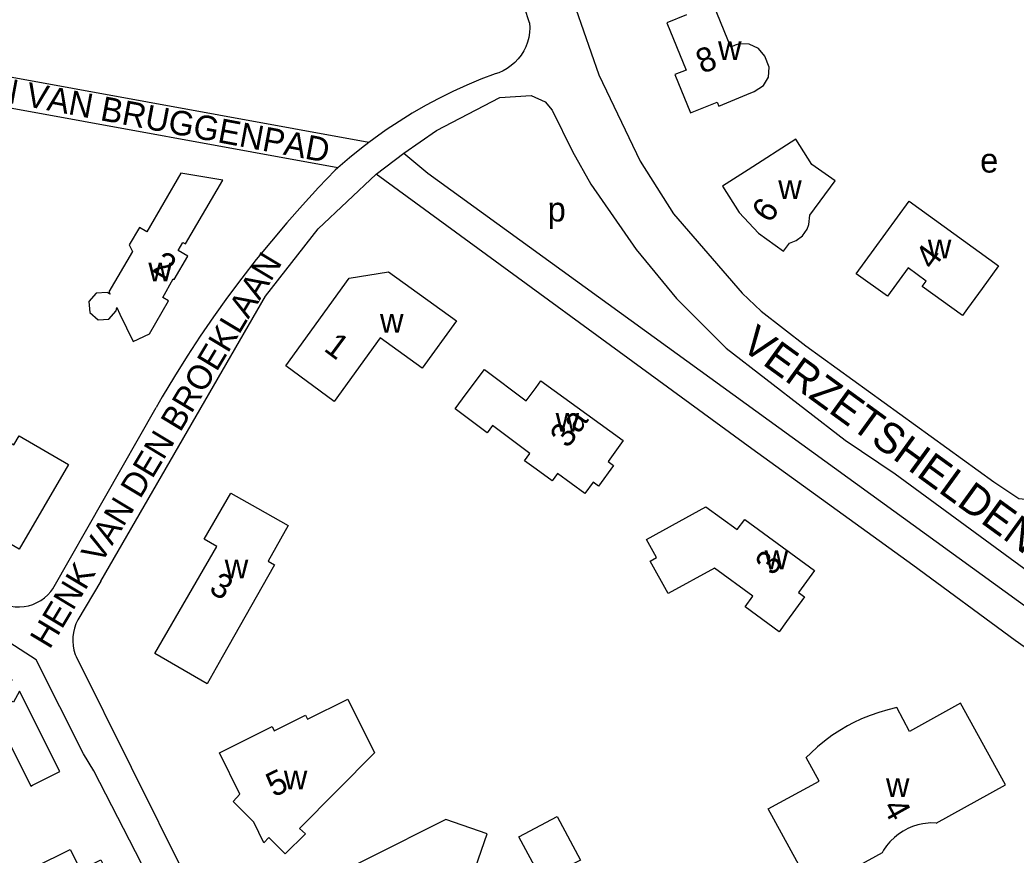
# Model space of a CAD drawing. Extents: x 156721 to 158827, y 386657 to 388950.
# Drawn here: x 158415.3 to 158578.8, y 387103.3 to 387240.4 of the extents above; entities that cross this region are included whole.
import ezdxf

# ---------------------------------------------------------------- set-up
doc = ezdxf.new("R2010")
doc.units = 0
for name, color, linetype in [('BLT_Basislijn', 7, 'Continuous'), ('BLT_Bebouwing', 7, 'Continuous'), ('BLT_Centroide', 7, 'Continuous'), ('BLT_Huisnummer', 7, 'Continuous'), ('BLT_Straatnaam', 7, 'Continuous'), ('BLT_Straatnaam_verkleind', 7, 'Continuous')]:
    doc.layers.add(name, color=color, linetype=linetype)

msp = doc.modelspace()

# ---------------------------------------------------------------- linework, layer by layer
at = {"layer": 'BLT_Basislijn'}
for p, q in [((158472.56, 387220.28), (158410.32, 387231.61)), ((158467.47, 387216.13), (158409.43, 387226.69)), ((158473.74, 387215.05), (158478.32, 387218.52)), ((158467.47, 387216.13), (158467, 387215.7)), ((158420.66, 387147), (158437.63, 387176.77)), ((158428.56, 387148.23), (158424.77, 387141.89)), ((158424.49, 387135.91), (158447.26, 387090.06))]:
    msp.add_line(p, q, dxfattribs=at)
for points in [[(158505.3, 387245.88), (158510.3, 387231.39), (158517.1, 387217.21), (158519.85, 387212.88)], [(158498.93, 387239.89), (158498.12, 387242.44), (158498.08, 387242.56)], [(158498.93, 387239.89), (158498.97, 387239.1), (158498.93, 387238.3), (158498.81, 387237.52), (158498.61, 387236.75), (158498.34, 387236), (158497.99, 387235.29), (158497.57, 387234.61), (158497.09, 387233.99), (158496.54, 387233.41), (158495.94, 387232.89), (158495.29, 387232.43), (158494.6, 387232.04), (158493.87, 387231.73), (158493.31, 387231.54)], [(158493.31, 387231.54), (158490.95, 387230.64), (158488.63, 387229.67), (158486.33, 387228.62), (158484.07, 387227.51), (158481.84, 387226.32), (158479.65, 387225.06), (158477.51, 387223.74), (158475.41, 387222.34), (158473.35, 387220.88), (158472.56, 387220.28)], [(158478.32, 387218.52), (158483.64, 387222.22), (158494.08, 387227.65), (158499.19, 387227.96), (158501.52, 387226.92), (158502.66, 387225.55), (158506, 387218.77), (158509.02, 387213.43), (158516.45, 387202.68), (158523.07, 387194.66), (158531.22, 387186.52), (158550.76, 387171.41), (158558.98, 387165.86), (158598.17, 387137.16), (158619.52, 387121.93)], [(158519.85, 387212.88), (158522.6, 387208.55), (158533.87, 387195.56), (158536.97, 387192.59), (158544.32, 387186.87), (158575.19, 387164.55), (158579.28, 387161.83), (158581.93, 387161.53), (158584.29, 387162.15), (158585.57, 387163.11), (158620.31, 387210.79), (158628.66, 387223)], [(158472.56, 387220.28), (158471.34, 387219.36), (158469.38, 387217.77), (158467.47, 387216.13)], [(158478.32, 387218.52), (158482.24, 387215.24), (158621.74, 387114.14)], [(158467, 387215.7), (158464.29, 387212.88), (158461.65, 387210), (158459.06, 387207.08), (158456.54, 387204.09), (158454.07, 387201.06), (158451.67, 387197.98), (158449.34, 387194.85), (158447.06, 387191.67), (158444.86, 387188.45), (158442.71, 387185.18), (158440.64, 387181.87), (158438.64, 387178.52), (158437.63, 387176.77)], [(158428.56, 387148.23), (158455.6, 387195.03), (158464.22, 387206.09), (158473.74, 387215.05)], [(158616.33, 387111.99), (158578.66, 387138.53), (158561.9, 387150.87), (158535.42, 387170), (158473.74, 387215.05)], [(158411.04, 387145.3), (158411.67, 387144.91), (158412.33, 387144.58), (158413.02, 387144.32), (158413.74, 387144.15), (158414.47, 387144.05), (158415.21, 387144.03), (158415.95, 387144.09), (158416.67, 387144.23), (158417.38, 387144.45), (158418.06, 387144.74), (158418.7, 387145.1), (158419.3, 387145.53), (158419.85, 387146.03), (158420.34, 387146.58), (158420.66, 387147)], [(158436.22, 387100), (158427.37, 387117.12), (158425.68, 387119.9), (158417.95, 387135.33), (158406.45, 387142.71), (158403.96, 387143.98), (158402.3, 387144.13), (158400.84, 387143.6), (158399.98, 387142.83), (158393.26, 387133.25), (158385.79, 387126.32), (158381.38, 387123.03), (158334.81, 387100), (158332.2, 387098.93), (158321.4, 387093.21), (158308.13, 387087.3), (158295.69, 387081.35)], [(158424.77, 387141.89), (158424.45, 387141.24), (158424.2, 387140.55), (158424.03, 387139.84), (158423.93, 387139.11), (158423.92, 387138.38), (158423.99, 387137.65), (158424.13, 387136.93), (158424.35, 387136.24), (158424.49, 387135.91)], [(158446.71, 387079.49), (158447.18, 387078.69), (158476.62, 387093.49), (158486.23, 387090.17), (158491.96, 387106.79), (158485.19, 387109.12), (158447.26, 387090.06)]]:
    msp.add_lwpolyline(points, dxfattribs=at)
at = {"layer": 'BLT_Bebouwing'}
for points in [[(158534.62, 387228.15), (158535.84, 387228.65), (158537.36, 387229.63), (158538.2, 387230.98), (158538.29, 387232.62), (158537.59, 387234.46), (158536.51, 387235.72), (158534.99, 387236.42), (158533.41, 387236.48), (158532.72, 387236.24), (158531.98, 387235.94), (158529.21, 387242.77)], [(158524.72, 387241.25), (158521.49, 387239.93), (158524.66, 387232.16), (158522.82, 387231.41), (158525.38, 387225.12), (158529.73, 387226.91), (158530, 387226.25), (158534.62, 387228.15)], [(158545.31, 387216.65), (158542.66, 387220.79), (158534.82, 387215.78), (158530.61, 387213.08), (158533.36, 387208.76), (158536.53, 387205.41), (158540.66, 387202.42), (158541.64, 387203.75), (158542.7, 387204.16), (158543.77, 387204.94), (158544.52, 387206.04), (158544.81, 387206.79)], [(158440.43, 387197.86), (158440.61, 387197.76), (158442.85, 387201.63), (158441.26, 387202.56), (158442.02, 387203.86), (158442.45, 387203.61), (158448.59, 387214.07), (158441.68, 387215.26), (158436.08, 387205.61), (158434.87, 387206.32), (158433.2, 387203.48), (158433.73, 387202.38), (158429.87, 387195.77), (158430.06, 387195.37), (158429.57, 387195.62), (158427.77, 387195.54), (158426.6, 387194.18), (158426.72, 387192.36), (158428.08, 387191.15), (158429.88, 387191.26), (158431.05, 387192.62), (158431.15, 387193.16), (158431.68, 387192.08), (158433.88, 387187.59), (158436.52, 387188.88), (158439.65, 387194.26), (158438.73, 387194.8), (158440.43, 387197.86)], [(158544.81, 387206.79), (158544.97, 387208.33), (158549.1, 387213.97), (158545.31, 387216.65)], [(158573.26, 387196.31), (158572.67, 387195.5), (158570.87, 387193.02), (158570.02, 387191.84), (158563.42, 387196.63), (158564.07, 387197.53), (158561.09, 387199.7), (158557.69, 387195.02), (158552.57, 387198.71), (158555.52, 387202.75), (158561.29, 387210.66), (158575.95, 387200.02), (158573.26, 387196.31)], [(158500, 387180.06), (158500.8, 387181.12), (158514.32, 387171.32), (158511.84, 387167.9), (158512.74, 387167.25), (158510.27, 387163.86), (158509.37, 387164.51), (158508.04, 387162.66), (158503.54, 387165.93), (158502.66, 387164.71), (158500, 387166.65), (158498.11, 387168.02), (158499.01, 387169.22), (158492.85, 387173.83), (158491.96, 387172.63), (158486.72, 387176.55), (158488.54, 387178.98), (158491.53, 387182.98), (158498.36, 387177.87), (158500, 387180.06)], [(158454.26, 387160.23), (158459.32, 387157.38), (158456.02, 387151.52), (158457.04, 387150.95), (158448.48, 387135.75), (158446.03, 387131.39), (158437.41, 387136.38), (158447.6, 387153.95), (158445.53, 387155.15), (158449.9, 387162.68), (158454.26, 387160.23)], [(158541.13, 387141.64), (158539.9, 387139.96), (158534.32, 387144.02), (158535.62, 387145.79), (158529.33, 387150.41), (158521.68, 387146.22), (158518.73, 387151.55), (158519.79, 387152.14), (158518.16, 387155.08), (158523.5, 387158.04), (158527.87, 387160.47), (158533.05, 387156.73), (158534.27, 387158.39), (158545.75, 387150.03), (158543.1, 387146.39), (158544.07, 387145.68), (158541.13, 387141.64)], [(158417.33, 387114.74), (158421.79, 387116.99), (158415.21, 387130.19), (158414.19, 387128.39), (158412.47, 387129.36), (158414, 387132.07), (158403.98, 387137.9), (158401.08, 387132.92), (158401.95, 387132.38), (158399.96, 387128.9), (158403.46, 387126.87), (158403.16, 387126.35), (158407.49, 387123.85), (158408.79, 387123.1), (158411.11, 387127.11), (158412.84, 387126.11), (158412.04, 387124.73), (158417.07, 387114.61), (158417.33, 387114.74)], [(158469.11, 387128.88), (158473.48, 387120.09), (158461.19, 387107.67), (158462.13, 387106.75), (158458.83, 387103.48), (158456.15, 387106.16), (158455.3, 387105.32), (158453.66, 387108.67), (158450.25, 387112.1), (158451.39, 387113.27), (158448.01, 387120.08), (158455.13, 387123.61), (158456.69, 387124.39), (158457.03, 387123.71), (158462.15, 387126.25), (158462.49, 387125.59), (158469.11, 387128.88)], [(158559.22, 387127.49), (158557.75, 387127.14), (158556.29, 387126.72), (158554.86, 387126.22), (158553.46, 387125.65), (158552.09, 387125), (158551.17, 387124.51)], [(158569.71, 387128.24), (158561.34, 387123.6), (158559.22, 387127.49)], [(158565.71, 387108.55), (158577.08, 387114.8), (158569.71, 387128.24)], [(158551.17, 387124.51), (158549.87, 387123.75), (158548.6, 387122.91), (158547.39, 387122.01), (158546.22, 387121.05), (158545.1, 387120.03), (158544.36, 387119.29)], [(158556.84, 387103.68), (158550.15, 387100), (158545.5, 387097.44), (158544.1, 387100), (158538.13, 387110.87), (158546.49, 387115.44), (158544.36, 387119.29)], [(158501.37, 387095.91), (158500.1, 387096.37), (158501, 387099.15), (158500.55, 387100), (158497.18, 387106.26), (158503.46, 387109.62), (158507.29, 387102.46), (158506.12, 387101.83), (158508.14, 387098.04), (158507.23, 387095.31), (158510.99, 387094.05), (158506.31, 387079.79), (158504.48, 387080.37), (158503.98, 387079.51), (158503.23, 387078.82), (158502.28, 387078.43), (158501.22, 387078.37), (158500.23, 387078.7), (158499.43, 387079.38), (158498.9, 387080.27), (158498.68, 387081.29), (158498.85, 387082.25), (158497.06, 387082.86), (158501.37, 387095.91)], [(158563.52, 387108.42), (158562.67, 387108.23), (158561.84, 387107.97), (158561.03, 387107.63), (158560.27, 387107.21), (158559.54, 387106.73), (158558.86, 387106.19), (158558.23, 387105.58), (158558.12, 387105.46)], [(158565.71, 387108.55), (158564.84, 387108.56), (158563.98, 387108.49), (158563.52, 387108.42)], [(158422.08, 387092.35), (158418.29, 387100), (158417.64, 387101.32), (158423.53, 387104.2), (158425.2, 387100.85), (158428.56, 387102.51), (158429.78, 387100), (158434.85, 387089.65), (158428.62, 387086.54), (158429.56, 387084.66), (158422.83, 387081.33), (158421.9, 387083.22), (158419.65, 387082.11), (158416.06, 387089.38), (158422.08, 387092.35)], [(158558.12, 387105.46), (158557.56, 387104.79), (158557.07, 387104.07), (158556.84, 387103.68)]]:
    msp.add_lwpolyline(points, dxfattribs=at)
for points in [[(158458.92, 387183.62), (158469.32, 387198), (158475.79, 387199.05), (158486.92, 387191), (158481.29, 387183.21), (158474.41, 387188.18), (158466.87, 387177.75)], [(158398.86, 387162.92), (158400.4, 387165.55), (158396.81, 387167.64), (158398.46, 387170.47), (158402.05, 387168.38), (158403.6, 387171.05), (158404.17, 387170.71), (158405.5, 387173), (158406.88, 387173.87), (158408.79, 387173.83), (158414.26, 387170.65), (158415.12, 387172.11), (158423.22, 387167.39), (158415.14, 387153.48)]]:
    msp.add_lwpolyline(points, close=True, dxfattribs=at)

# ---------------------------------------------------------------- texts
at = {"layer": 'BLT_Centroide'}
for s, p in [('w', (158529.89, 387233.81)), ('e', (158572.93, 387215.33)), ('w', (158539.77, 387211)), ('p', (158501.91, 387207.3)), ('w', (158564.34, 387201.25)), ('w', (158436.36, 387197.45)), ('w', (158474.38, 387189.03)), ('w', (158503.22, 387172.81)), ('w', (158537.55, 387150.22)), ('w', (158448.89, 387148.7)), ('w', (158458.59, 387114.09)), ('w', (158557.46, 387112.84))]:
    msp.add_text(s, height=4, dxfattribs=at).set_placement(p)
at = {"layer": 'BLT_Huisnummer'}
for s, rotation, p in [('8', 22.3397, (158527.29, 387231.49)), ('6', 53.8849, (158538.35, 387206.85)), ('2', 329.5802, (158436.78, 387199.21)), ('4', 54.0358, (158565.18, 387199.19)), ('1', 323.302, (158464.98, 387186.2)), ('3a', 54.0216, (158505.23, 387169.93)), ('3', 53.9371, (158538.92, 387148.98)), ('3', 329.9532, (158446.12, 387146.5)), ('5', 26.4216, (158456.96, 387112.71)), ('4', 299.2045, (158556.82, 387111.16))]:
    msp.add_text(s, height=4, rotation=rotation, dxfattribs=at).set_placement(p)
at = {"layer": 'BLT_Straatnaam'}
msp.add_text('VERZETSHELDENLAAN', height=5, rotation=324.0497, dxfattribs=at).set_placement((158533.41, 387186.54))
at = {"layer": 'BLT_Straatnaam_verkleind'}
for s, rotation, p in [('RIEN VAN BRUGGENPAD', 349.364, (158402, 387228.89)), ('HENK VAN DEN BROEKLAAN', 58.9721, (158420.13, 387136.92))]:
    msp.add_text(s, height=4, rotation=rotation, dxfattribs=at).set_placement(p)

doc.saveas('drawing.dxf')
